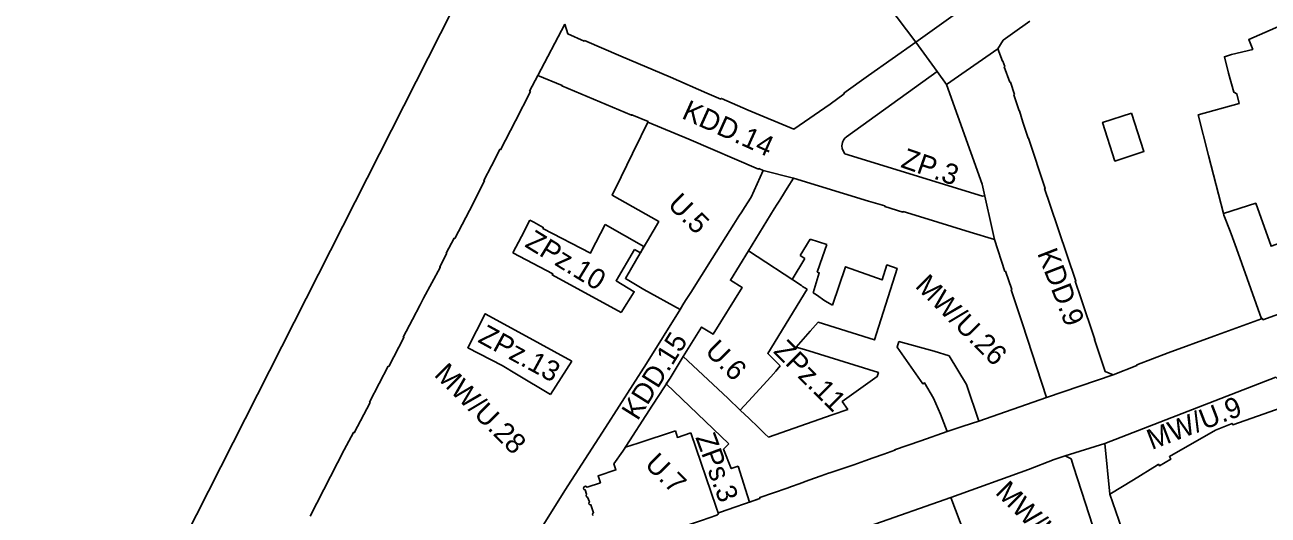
# Model space of a CAD drawing. Extents: x 7423835 to 7425280, y 5546086 to 5547600.
# Drawn here: x 7424227.3 to 7424593.5, y 5546834 to 5546978.5 of the extents above; entities that cross this region are included whole.
import ezdxf

# ---------------------------------------------------------------- set-up
doc = ezdxf.new("R2010")
doc.units = 0
for name, color, linetype in [('linie rozgraniczające', 7, 'Continuous'), ('nieprzekraczalne linie zabudowy', 7, 'Continuous'), ('obowiazujace linie zabudowy', 7, 'Continuous'), ('przeznaczenia terenów', 7, 'Continuous')]:
    doc.layers.add(name, color=color, linetype=linetype)

msp = doc.modelspace()

# ---------------------------------------------------------------- linework, layer by layer
at = {"layer": 'linie rozgraniczające'}
for p, q in [((7424504.88, 5546984.18), (7424489.79, 5546973.41)), ((7424386.34, 5546978.7), (7424378.39, 5546963.59)), ((7424495.98, 5546964.75), (7424489.79, 5546973.41)), ((7424444.79, 5546935.59), (7424453.74, 5546933.3)), ((7424455.63, 5546910.56), (7424458.61, 5546915.28)), ((7424458.61, 5546915.28), (7424463.49, 5546913.77)), ((7424462.22, 5546910.09), (7424463.49, 5546913.77)), ((7424453.3, 5546903.47), (7424457.1, 5546909.64)), ((7424457.1, 5546909.64), (7424455.63, 5546910.56)), ((7424460.66, 5546905.59), (7424462.22, 5546910.09)), ((7424388.38, 5546879.42), (7424382.18, 5546869.51)), ((7424547.9, 5546875.38), (7424528.24, 5546868.65)), ((7424416.25, 5546872.7), (7424434.67, 5546855.02)), ((7424545.36, 5546855.11), (7424533.77, 5546851.51))]:
    msp.add_line(p, q, dxfattribs=at)
for points in [[(7424213.38, 5546724.52), (7424267.06, 5546812.79), (7424421.63, 5547117.9)], [(7424386.34, 5546978.7), (7424387.21, 5546975.87), (7424392.09, 5546973.68), (7424392.17, 5546973.85), (7424402.9, 5546969.28), (7424417.44, 5546963.05), (7424428.2, 5546958.37), (7424432.36, 5546956.6), (7424432.49, 5546956.81), (7424440.32, 5546953.37), (7424453.82, 5546947.7), (7424464.5, 5546955.15), (7424468.67, 5546958.19), (7424468.57, 5546958.33), (7424475.85, 5546963.56), (7424489.79, 5546973.41), (7424478.72, 5546988.05)], [(7424523.35, 5546979.58), (7424518.2, 5546975.95), (7424515.46, 5546973.92), (7424513.94, 5546971.42), (7424515.24, 5546967.74), (7424515.37, 5546967.79), (7424515.94, 5546966.17), (7424515.77, 5546966.1), (7424517.47, 5546961.57), (7424517.59, 5546961.61), (7424518.76, 5546957.98), (7424518.63, 5546957.88), (7424520.14, 5546953.12), (7424520.29, 5546953.16), (7424521.3, 5546949.83), (7424522.8, 5546945.11), (7424522.9, 5546945.12), (7424527.85, 5546930.27), (7424527.68, 5546930.21), (7424529.21, 5546925.67), (7424536.89, 5546902.99), (7424536.7, 5546902.92), (7424538.34, 5546898.04), (7424542.49, 5546885.8), (7424542.32, 5546885.75), (7424545.55, 5546876.31), (7424547.9, 5546875.38)], [(7424600.37, 5546973.96), (7424597.25, 5546978.25), (7424587.81, 5546974.2), (7424588.98, 5546971.24), (7424582.7, 5546969.73), (7424580.63, 5546969.1), (7424581.87, 5546964.22), (7424583.37, 5546958.63), (7424584.27, 5546958.18), (7424585.02, 5546955.3)], [(7424513.94, 5546971.42), (7424498.74, 5546960.88), (7424495.98, 5546964.75), (7424469.33, 5546945.52), (7424468.85, 5546945.08), (7424468.44, 5546944.53), (7424468.23, 5546944.07), (7424468.17, 5546943.8)], [(7424378.39, 5546963.59), (7424375.99, 5546958.95), (7424376.22, 5546958.83), (7424371.81, 5546950.24), (7424367.38, 5546941.68), (7424367.19, 5546941.78), (7424364.73, 5546936.98), (7424362.47, 5546932.6), (7424362.71, 5546932.5), (7424358.27, 5546923.81), (7424353.95, 5546915.5), (7424353.73, 5546915.6), (7424351.43, 5546911.16), (7424351.55, 5546911.1), (7424349.53, 5546907.1), (7424349.65, 5546907.01), (7424344.79, 5546897.98), (7424343.75, 5546895.98), (7424341.46, 5546891.66), (7424338.76, 5546886.47), (7424338.96, 5546886.37), (7424334.5, 5546877.83), (7424334.35, 5546877.9), (7424331.71, 5546872.78), (7424328.87, 5546867.32), (7424329.03, 5546867.23), (7424324.32, 5546858.25), (7424324.09, 5546858.39), (7424321.42, 5546853.23), (7424311.33, 5546833.75)], [(7424378.18, 5546828.24), (7424386.41, 5546841.23), (7424398.35, 5546859.82), (7424410.4, 5546878.65), (7424420.31, 5546894.62), (7424420.31, 5546894.62), (7424421.13, 5546895.93), (7424421.95, 5546897.24), (7424422.69, 5546898.41), (7424423.43, 5546899.57), (7424429.79, 5546909.65), (7424436.15, 5546919.73), (7424437.63, 5546922.08), (7424438.48, 5546923.38), (7424439.32, 5546924.68), (7424439.32, 5546924.68), (7424441.26, 5546927.73), (7424444.79, 5546935.59), (7424443.49, 5546936.13), (7424443.43, 5546935.98), (7424422.85, 5546944.81), (7424410.79, 5546949.76), (7424410.88, 5546950.01), (7424406.09, 5546952), (7424406.03, 5546951.86), (7424385.51, 5546960.47), (7424385.57, 5546960.63), (7424378.39, 5546963.59)], [(7424498.74, 5546960.88), (7424509.25, 5546931.58), (7424512.9, 5546915.2)], [(7424585.02, 5546955.3), (7424572.93, 5546951.94), (7424575.97, 5546939.99), (7424580.32, 5546922.85), (7424580.45, 5546922.44), (7424582.31, 5546917.67), (7424582.97, 5546915.83), (7424584.2, 5546912.53), (7424591.55, 5546891.85)], [(7424410.79, 5546949.76), (7424406.79, 5546941.59), (7424406.54, 5546941.06), (7424406.28, 5546940.53), (7424402.98, 5546933.73), (7424402.97, 5546933.7), (7424400.29, 5546928.33), (7424414.03, 5546920.49), (7424412.36, 5546917.67), (7424412.36, 5546917.67), (7424410.68, 5546914.86), (7424410.68, 5546914.86), (7424409.14, 5546912.21), (7424407.6, 5546909.57), (7424404.2, 5546903.77), (7424409.59, 5546900.49), (7424420.31, 5546894.62)], [(7424468.17, 5546943.8), (7424467.95, 5546942.86), (7424468.03, 5546942.06), (7424468.32, 5546941.33), (7424468.87, 5546940.51), (7424509.42, 5546927.97), (7424510.04, 5546928.05)], [(7424453.74, 5546933.3), (7424451.87, 5546930.33), (7424449.99, 5546927.35), (7424449.46, 5546926.51), (7424448.93, 5546925.67), (7424448.05, 5546924.25), (7424440.5, 5546911.93), (7424456.05, 5546901.65), (7424456.41, 5546901.41), (7424457.74, 5546900.58)], [(7424453.74, 5546933.3), (7424475.82, 5546926.56), (7424480.64, 5546925.11), (7424480.58, 5546924.96), (7424485.96, 5546923.33), (7424486.01, 5546923.47), (7424490.8, 5546922.02), (7424505.71, 5546917.4), (7424512.9, 5546915.2), (7424516, 5546905.81), (7424516.15, 5546905.86), (7424517.98, 5546900.45), (7424517.83, 5546900.4), (7424521.18, 5546890.37), (7424528.24, 5546868.65), (7424508.34, 5546861.72), (7424503.64, 5546860.21), (7424498.94, 5546858.7), (7424491.22, 5546855.95), (7424483.5, 5546853.21), (7424483.56, 5546853.14), (7424483.56, 5546853.14), (7424480.35, 5546852.01), (7424477.14, 5546850.89), (7424474.75, 5546850.02), (7424471.48, 5546848.86), (7424468.2, 5546847.71), (7424464.67, 5546846.56), (7424464.37, 5546846.45), (7424464.07, 5546846.34), (7424462.96, 5546845.94), (7424461.85, 5546845.55), (7424458.21, 5546844.27), (7424455.39, 5546843.27), (7424453.15, 5546842.45), (7424451.81, 5546841.92)], [(7424580.32, 5546922.85), (7424589.85, 5546925.89), (7424594.37, 5546913.26), (7424616.46, 5546921.11), (7424612.99, 5546930.89), (7424624.28, 5546934.78)], [(7424371.1, 5546911.3), (7424373.61, 5546916.16), (7424376.08, 5546920.93)], [(7424398.21, 5546919.68), (7424394.15, 5546911.68), (7424393.9, 5546911.2), (7424379.9, 5546918.5), (7424380.03, 5546918.79), (7424377.23, 5546920.31), (7424376.08, 5546920.93)], [(7424398.21, 5546919.68), (7424409.67, 5546913.13), (7424408.61, 5546911.3), (7424406.88, 5546912.3)], [(7424547.9, 5546875.38), (7424554.86, 5546878.13), (7424554.8, 5546878.26), (7424564.11, 5546881.85), (7424577.56, 5546886.72), (7424591.55, 5546891.85), (7424591.81, 5546891.95), (7424591.94, 5546891.6), (7424601.42, 5546894.98), (7424601.32, 5546895.28), (7424622.5, 5546902.83), (7424622.61, 5546902.55), (7424632.09, 5546905.93), (7424631.95, 5546906.36), (7424632.21, 5546906.45), (7424631.94, 5546907.22), (7424644.01, 5546911.45), (7424643.29, 5546913.33), (7424643.29, 5546913.33)], [(7424371.1, 5546911.3), (7424382.83, 5546905.16), (7424382.65, 5546904.81), (7424402.91, 5546893.67)], [(7424406.88, 5546912.3), (7424401.48, 5546903.08), (7424406.81, 5546899.84), (7424402.91, 5546893.67)], [(7424440.5, 5546911.93), (7424435.14, 5546903.2), (7424438.55, 5546901.09), (7424430.02, 5546887.29), (7424426.64, 5546889.44), (7424421.24, 5546880.75)], [(7424478.19, 5546887.53), (7424484.21, 5546906.72), (7424481.23, 5546907.72), (7424479.84, 5546903.31), (7424469.06, 5546907.21), (7424465.24, 5546895.86)], [(7424460.66, 5546905.59), (7424461.28, 5546905.41), (7424459.52, 5546899.47)], [(7424457.74, 5546900.58), (7424446.12, 5546881.63), (7424449.81, 5546878)], [(7424459.52, 5546899.47), (7424460.45, 5546898.89), (7424462.98, 5546897.19), (7424465.24, 5546895.86)], [(7424382.18, 5546869.51), (7424372.11, 5546875.54), (7424367.88, 5546878.08), (7424357.78, 5546883.35), (7424362.95, 5546893.35), (7424373.9, 5546887.35), (7424388.38, 5546879.42)], [(7424469.73, 5546865.16), (7424468.08, 5546867.46), (7424478.32, 5546874.85), (7424478.7, 5546876.03), (7424456.97, 5546882.77), (7424454.49, 5546883.54), (7424458.63, 5546888.2), (7424460.96, 5546890.84), (7424477.59, 5546885.62), (7424478.19, 5546887.53)], [(7424394.66, 5546833.91), (7424394.53, 5546834.28), (7424394.71, 5546834.64), (7424394.84, 5546834.69), (7424394.05, 5546837.05), (7424393.9, 5546837.01), (7424393.55, 5546837.15), (7424393.42, 5546837.55), (7424393.63, 5546837.93), (7424393.09, 5546839.27), (7424392.75, 5546839.43), (7424392.62, 5546839.83), (7424392.79, 5546840.19), (7424392.36, 5546841.44), (7424392, 5546841.59), (7424391.87, 5546842), (7424392.05, 5546842.34), (7424392.41, 5546842.51), (7424392.95, 5546842.26), (7424396.87, 5546843.55), (7424396.14, 5546845.61), (7424401.39, 5546847.32), (7424400.84, 5546849.09), (7424403.44, 5546852.86), (7424412.16, 5546866.37), (7424417.35, 5546874.41), (7424421.24, 5546880.75), (7424434.35, 5546868.43), (7424438.03, 5546864.95), (7424440.66, 5546862.44), (7424443.29, 5546859.92), (7424445.3, 5546857.99), (7424446.34, 5546856.99)], [(7424449.81, 5546878), (7424448.92, 5546876.95), (7424448.52, 5546876.47), (7424447.01, 5546874.8), (7424440.42, 5546867.57), (7424438.03, 5546864.95)], [(7424602.91, 5546867.57), (7424595.78, 5546874.63), (7424545.36, 5546855.11)], [(7424545.36, 5546855.11), (7424546.87, 5546840.16), (7424553.83, 5546844.45), (7424560.78, 5546848.73), (7424561.2, 5546848.98), (7424561.48, 5546848.55), (7424564.87, 5546850.55), (7424564.41, 5546851.25), (7424578.02, 5546859.03), (7424582.88, 5546861.02), (7424583.08, 5546860.66), (7424602.91, 5546867.57)], [(7424446.34, 5546856.99), (7424465.14, 5546863.56), (7424469.73, 5546865.16)], [(7424418.95, 5546858.81), (7424407.98, 5546855.25), (7424404.19, 5546854.02)], [(7424418.95, 5546858.81), (7424419.54, 5546856.91), (7424423.51, 5546858.22)], [(7424423.51, 5546858.22), (7424430.93, 5546836.39), (7424431.58, 5546834.43)], [(7424437.37, 5546848.41), (7424435.37, 5546847.73), (7424433.14, 5546853.46), (7424434.67, 5546855.02)], [(7424530.89, 5546811.29), (7424545.11, 5546820.7), (7424538.49, 5546841.09), (7424536.21, 5546848.35), (7424535.46, 5546850.59), (7424533.77, 5546851.51), (7424530.46, 5546850.39), (7424522.88, 5546847.46), (7424500.08, 5546839.22)], [(7424437.37, 5546848.41), (7424439.56, 5546841.61), (7424440.77, 5546837.87)], [(7424451.81, 5546841.92), (7424443.75, 5546839.21), (7424443.84, 5546838.94), (7424431.95, 5546834.78), (7424431.16, 5546834.04), (7424426.61, 5546832.41)], [(7424546.87, 5546840.16), (7424553.07, 5546822.35), (7424558.38, 5546806.12), (7424562.73, 5546793.62), (7424565.74, 5546781.7), (7424566.26, 5546779.13), (7424567.08, 5546775.74), (7424567.21, 5546775.74), (7424572.61, 5546757.78), (7424579.36, 5546736.66), (7424581.27, 5546729.79), (7424582.77, 5546725.18), (7424583.4, 5546722.97), (7424583.5, 5546722.97), (7424583.6, 5546722.64)], [(7424476.01, 5546830.71), (7424500.08, 5546839.22), (7424504.17, 5546828.3), (7424504.92, 5546826.44)]]:
    msp.add_lwpolyline(points, dxfattribs=at)
at = {"layer": 'nieprzekraczalne linie zabudowy'}
msp.add_lwpolyline([(7424553.3, 5546952.49), (7424556.94, 5546941.16), (7424548.39, 5546938.33), (7424544.73, 5546949.74)], close=True, dxfattribs=at)
at = {"layer": 'obowiazujace linie zabudowy'}
for p, q in [((7424484.74, 5546885.19), (7424495.11, 5546882.33)), ((7424504.62, 5546872.46), (7424508.34, 5546861.72)), ((7424497.03, 5546863.8), (7424494.99, 5546868.43)), ((7424498.94, 5546858.7), (7424497.03, 5546863.8))]:
    msp.add_line(p, q, dxfattribs=at)
for points in [[(7424386.34, 5546978.7), (7424387.21, 5546975.87), (7424392.09, 5546973.68), (7424392.17, 5546973.85), (7424402.9, 5546969.28), (7424417.44, 5546963.05), (7424428.2, 5546958.37), (7424432.36, 5546956.6), (7424432.49, 5546956.81), (7424440.32, 5546953.37), (7424453.82, 5546947.7), (7424464.5, 5546955.15), (7424468.67, 5546958.19), (7424468.57, 5546958.33), (7424475.85, 5546963.56), (7424489.79, 5546973.41), (7424478.72, 5546988.05)], [(7424523.35, 5546979.58), (7424518.2, 5546975.95), (7424515.46, 5546973.92), (7424513.94, 5546971.42), (7424515.24, 5546967.74), (7424515.37, 5546967.79), (7424515.94, 5546966.17), (7424515.77, 5546966.1), (7424517.47, 5546961.57), (7424517.59, 5546961.61), (7424518.76, 5546957.98), (7424518.63, 5546957.88), (7424520.14, 5546953.12), (7424520.29, 5546953.16), (7424521.3, 5546949.83), (7424522.8, 5546945.11), (7424522.9, 5546945.12), (7424527.85, 5546930.27), (7424527.68, 5546930.21), (7424529.21, 5546925.67), (7424536.89, 5546902.99), (7424536.7, 5546902.92), (7424538.34, 5546898.04), (7424542.49, 5546885.8), (7424542.32, 5546885.75), (7424545.55, 5546876.31), (7424547.9, 5546875.38)], [(7424378.39, 5546963.59), (7424375.99, 5546958.95), (7424376.22, 5546958.83), (7424371.81, 5546950.24), (7424367.38, 5546941.68), (7424367.19, 5546941.78), (7424364.73, 5546936.98), (7424362.47, 5546932.6), (7424362.71, 5546932.5), (7424358.27, 5546923.81), (7424353.95, 5546915.5), (7424353.73, 5546915.6), (7424351.43, 5546911.16), (7424351.55, 5546911.1), (7424349.53, 5546907.1), (7424349.65, 5546907.01), (7424344.79, 5546897.98), (7424343.75, 5546895.98), (7424341.46, 5546891.66), (7424338.76, 5546886.47), (7424338.96, 5546886.37), (7424334.5, 5546877.83), (7424334.35, 5546877.9), (7424331.71, 5546872.78), (7424328.87, 5546867.32), (7424329.03, 5546867.23), (7424324.32, 5546858.25), (7424324.09, 5546858.39), (7424321.42, 5546853.23), (7424311.33, 5546833.75)], [(7424378.18, 5546828.24), (7424386.41, 5546841.23), (7424398.35, 5546859.82), (7424410.4, 5546878.65), (7424420.31, 5546894.62), (7424420.31, 5546894.62), (7424421.13, 5546895.93), (7424421.95, 5546897.24), (7424422.69, 5546898.41), (7424423.43, 5546899.57), (7424429.79, 5546909.65), (7424436.15, 5546919.73), (7424437.63, 5546922.08), (7424438.48, 5546923.38), (7424439.32, 5546924.68), (7424439.32, 5546924.68), (7424441.26, 5546927.73), (7424444.79, 5546935.59), (7424443.49, 5546936.13), (7424443.43, 5546935.98), (7424422.85, 5546944.81), (7424410.79, 5546949.76), (7424410.88, 5546950.01), (7424406.09, 5546952), (7424406.03, 5546951.86), (7424385.51, 5546960.47), (7424385.57, 5546960.63), (7424378.39, 5546963.59)], [(7424453.74, 5546933.3), (7424451.87, 5546930.33), (7424449.99, 5546927.35), (7424449.46, 5546926.51), (7424448.93, 5546925.67), (7424448.05, 5546924.25), (7424440.5, 5546911.93)], [(7424508.34, 5546861.72), (7424508.34, 5546861.72), (7424528.24, 5546868.65), (7424521.18, 5546890.37), (7424517.83, 5546900.4), (7424517.98, 5546900.45), (7424516.15, 5546905.86), (7424516, 5546905.81), (7424512.9, 5546915.2), (7424505.71, 5546917.4), (7424490.8, 5546922.02), (7424486.01, 5546923.47), (7424485.96, 5546923.33), (7424480.58, 5546924.96), (7424480.64, 5546925.11), (7424475.82, 5546926.56), (7424453.74, 5546933.3)], [(7424440.5, 5546911.93), (7424435.14, 5546903.2), (7424438.55, 5546901.09), (7424430.02, 5546887.29), (7424426.64, 5546889.44), (7424421.24, 5546880.75)], [(7424547.9, 5546875.38), (7424554.86, 5546878.13), (7424554.8, 5546878.26), (7424564.11, 5546881.85), (7424577.56, 5546886.72), (7424591.55, 5546891.85), (7424591.81, 5546891.95), (7424591.94, 5546891.6), (7424601.42, 5546894.98), (7424601.32, 5546895.28), (7424622.5, 5546902.83), (7424622.61, 5546902.55), (7424632.09, 5546905.93), (7424631.95, 5546906.36), (7424632.21, 5546906.45), (7424631.94, 5546907.22)], [(7424494.99, 5546868.43), (7424492.29, 5546873.02), (7424491.8, 5546872.71), (7424484.24, 5546883.53), (7424484.74, 5546885.19)], [(7424421.24, 5546880.75), (7424417.35, 5546874.41), (7424416.25, 5546872.7)], [(7424495.11, 5546882.33), (7424499.53, 5546880.97), (7424504.62, 5546872.46)], [(7424602.91, 5546867.57), (7424595.78, 5546874.63), (7424545.36, 5546855.11)], [(7424451.81, 5546841.92), (7424453.15, 5546842.45), (7424455.39, 5546843.27), (7424458.21, 5546844.27), (7424461.85, 5546845.55), (7424462.96, 5546845.94), (7424464.07, 5546846.34), (7424464.37, 5546846.45), (7424464.67, 5546846.56), (7424468.2, 5546847.71), (7424471.48, 5546848.86), (7424474.75, 5546850.02), (7424477.14, 5546850.89), (7424480.35, 5546852.01), (7424483.56, 5546853.14), (7424483.56, 5546853.14), (7424483.5, 5546853.21), (7424491.22, 5546855.95), (7424498.94, 5546858.7)], [(7424545.36, 5546855.11), (7424546.87, 5546840.16)], [(7424404.19, 5546854.02), (7424403.44, 5546852.86), (7424400.84, 5546849.09), (7424401.39, 5546847.32), (7424396.14, 5546845.61), (7424396.87, 5546843.55), (7424392.95, 5546842.26), (7424392.41, 5546842.51), (7424392.05, 5546842.34), (7424391.87, 5546842), (7424392, 5546841.59), (7424392.36, 5546841.44), (7424392.79, 5546840.19), (7424392.62, 5546839.83), (7424392.75, 5546839.43), (7424393.09, 5546839.27), (7424393.63, 5546837.93), (7424393.42, 5546837.55), (7424393.55, 5546837.15), (7424393.9, 5546837.01), (7424394.05, 5546837.05), (7424394.84, 5546834.69), (7424394.71, 5546834.64), (7424394.53, 5546834.28), (7424394.66, 5546833.91)], [(7424530.89, 5546811.29), (7424545.11, 5546820.7), (7424538.49, 5546841.09), (7424536.21, 5546848.35), (7424535.46, 5546850.59), (7424533.77, 5546851.51), (7424530.46, 5546850.39), (7424522.88, 5546847.46), (7424500.08, 5546839.22)], [(7424440.77, 5546837.87), (7424443.84, 5546838.94), (7424443.75, 5546839.21), (7424451.81, 5546841.92)], [(7424407.98, 5546826.26), (7424417.29, 5546829.33), (7424426.61, 5546832.41), (7424431.16, 5546834.04), (7424431.58, 5546834.43)]]:
    msp.add_lwpolyline(points, dxfattribs=at)

# ---------------------------------------------------------------- texts
at = {"layer": 'przeznaczenia terenów'}
for s, rotation, p in [('KDD.14', 335.7254, (7424420.49, 5546951.06)), ('ZP.3', 340.8024, (7424485.03, 5546936.62)), ('U.5', 314.9764, (7424416.38, 5546925.23)), ('ZPz.10', 328.5076, (7424374.3, 5546913.27)), ('KDD.9', 291.215, (7424525.43, 5546911.2)), ('MW/U.26', 314.9764, (7424489.26, 5546901.29)), ('ZPz.13', 331.3802, (7424360.47, 5546885.16)), ('KDD.15', 57.8864, (7424407.8, 5546861.61)), ('U.6', 314.9764, (7424427.37, 5546882.01)), ('ZPz.11', 314.9764, (7424447.51, 5546882.05)), ('MW/U.28', 314.9764, (7424347.64, 5546875.16)), ('MW/U.9', 21.0313, (7424559.23, 5546853.19)), ('ZPs.3', 290.3303, (7424424.76, 5546856.93)), ('U.7', 314.9764, (7424409.62, 5546848.66)), ('MW/U.24', 314.9764, (7424512.9, 5546840.43))]:
    msp.add_text(s, height=6, rotation=rotation, dxfattribs=at).set_placement(p)

doc.saveas('drawing.dxf')
